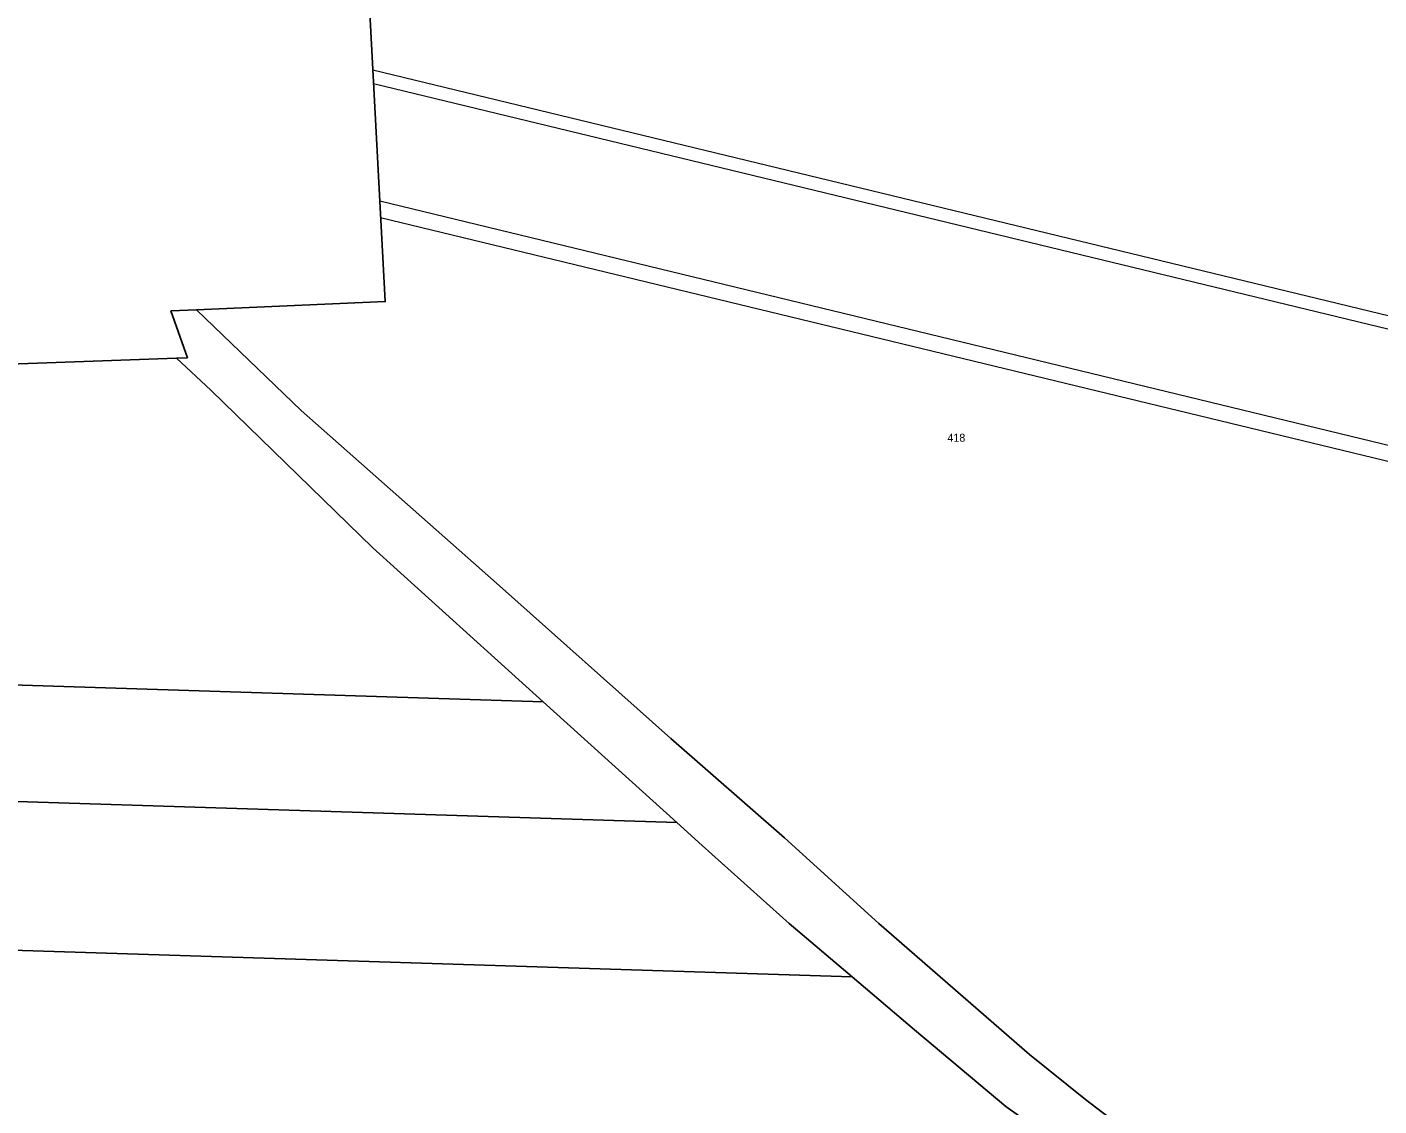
# Model space of a CAD drawing. Extents: x -769392 to -767038, y -1018329 to -1015269.
# Drawn here: x -768996.5 to -768709.3, y -1017593.3 to -1017364.2 of the extents above; entities that cross this region are included whole.
import ezdxf

# ---------------------------------------------------------------- set-up
doc = ezdxf.new("R2010")
doc.units = 0
doc.header["$LTSCALE"] = 0.68
doc.layers.add('1', color=7, linetype='Continuous', lineweight=25)
doc.layers.add('13', color=7, linetype='Continuous', lineweight=13)
doc.layers.add('2', color=7, linetype='Continuous')

msp = doc.modelspace()

# ---------------------------------------------------------------- linework, layer by layer
at = {"layer": '1'}
for p, q in [((-768960.52, -1017424.21), (-768965.92, -1017424.44)), ((-768965.92, -1017424.44), (-768962.39, -1017434.45)), ((-768962.39, -1017434.45), (-768964.75, -1017434.53)), ((-768886.87, -1017507.48), (-768858.49, -1017533.11))]:
    msp.add_line(p, q, dxfattribs=at)
for points in [[(-768925.48, -1017327.81), (-768920.42, -1017422.48), (-768960.52, -1017424.21)], [(-768705.75, -1017629.73), (-768712.89, -1017627.18), (-768730.41, -1017619.46), (-768742.74, -1017612.43), (-768755.47, -1017604.38), (-768771.64, -1017591.98), (-768783.52, -1017582.39), (-768815.53, -1017554.55), (-768835.62, -1017536.41), (-768859.73, -1017515.3), (-768896.78, -1017482.26), (-768938.25, -1017445.59), (-768960.52, -1017424.21)], [(-768964.75, -1017434.53), (-769023.87, -1017436.64), (-769121.63, -1017434.16)], [(-768964.75, -1017434.53), (-768957.47, -1017441.31), (-768923.05, -1017474.8), (-768886.87, -1017507.48)], [(-769327.22, -1017493.49), (-769201.31, -1017497.49), (-769006.44, -1017503.68), (-768886.87, -1017507.48)], [(-769332.43, -1017518.05), (-769200.3, -1017522.25), (-769005.38, -1017528.44), (-768858.49, -1017533.11)], [(-768858.49, -1017533.11), (-768853.1, -1017537.99), (-768834.59, -1017554.54), (-768821.21, -1017565.9)], [(-769339.08, -1017549.45), (-769200.78, -1017553.84), (-769006.43, -1017560.02), (-768821.21, -1017565.9)], [(-768821.21, -1017565.9), (-768807.98, -1017577.14), (-768788.56, -1017593.42), (-768781, -1017598.79)]]:
    msp.add_lwpolyline(points, dxfattribs=at)
at = {"layer": '13'}
for points in [[(-768922.9, -1017376.15), (-768700.67, -1017429.93), (-768692.59, -1017431.89), (-768681.07, -1017434.68), (-768680.77, -1017431.95), (-768691.95, -1017429.24), (-768700.37, -1017427.2), (-768923.05, -1017373.32)], [(-768921.38, -1017404.59), (-768701.84, -1017457.72), (-768699.01, -1017458.4), (-768681.98, -1017462.52), (-768681.87, -1017459.18), (-768698.24, -1017455.22), (-768701.73, -1017454.38), (-768921.56, -1017401.17)]]:
    msp.add_lwpolyline(points, close=True, dxfattribs=at)

# ---------------------------------------------------------------- texts
at = {"layer": '2'}
msp.add_text('418', height=1.7, dxfattribs=at).set_placement((-768800.98, -1017452.245))

doc.saveas('drawing.dxf')
